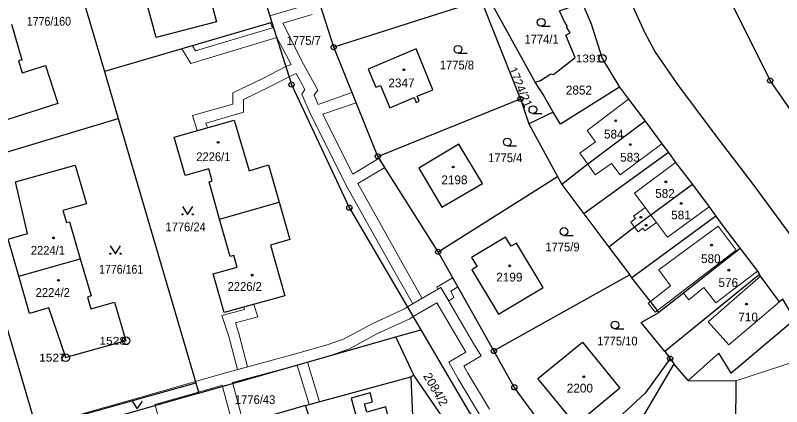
# Model space of a CAD drawing. Extents: x -679733 to -673243, y -1075091 to -1066557.
# Drawn here: x -676657.5 to -676509.5, y -1072340.3 to -1072264.6 of the extents above; entities that cross this region are included whole.
import ezdxf
from ezdxf.enums import TextEntityAlignment as Align

# ---------------------------------------------------------------- set-up
doc = ezdxf.new("R2010")
doc.units = 0
doc.header["$LTSCALE"] = 0.68
for name, color, linetype, lineweight in [('1', 7, 'Continuous', 25), ('13', 7, 'Continuous', 13), ('3', 7, 'Continuous', 25), ('4', 7, 'Continuous', 13), ('5', 7, 'Continuous', 25), ('8', 7, 'Continuous', 25)]:
    doc.layers.add(name, color=color, linetype=linetype, lineweight=lineweight)
doc.layers.add('2', color=7, linetype='Continuous')

msp = doc.modelspace()

# ---------------------------------------------------------------- linework, layer by layer
at = {"layer": '1'}
for p, q in [((-676621.45, -1072223.02), (-676607.94, -1072265.95)), ((-676650.7, -1072240.13), (-676640.33, -1072275.45)), ((-676557.11, -1072277.51), (-676565.21, -1072262.82)), ((-676559.93, -1072280.75), (-676558.34, -1072285.56)), ((-676668.3, -1072293.79), (-676637.65, -1072284.57)), ((-676531.34, -1072291.15), (-676547.67, -1072303)), ((-676575.84, -1072310.34), (-676552.78, -1072295.79)), ((-676618.06, -1072304), (-676606.53, -1072300.73)), ((-676547.67, -1072303), (-676542.82, -1072309.41)), ((-676522.18, -1072303.41), (-676538.38, -1072315.35)), ((-676542.82, -1072309.41), (-676538.81, -1072314.77)), ((-676656.87, -1072315.07), (-676644.98, -1072311.7)), ((-676538.81, -1072314.77), (-676565.06, -1072329.52)), ((-676580.53, -1072334.19), (-676584, -1072326.79)), ((-676527.49, -1072335.21), (-676530.28, -1072331.99)), ((-676601.48, -1072340.1), (-676581.08, -1072334.53)), ((-676580.53, -1072334.19), (-676581.08, -1072334.53)), ((-676571.12, -1072347.95), (-676580.53, -1072334.19)), ((-676648.79, -1072343.03), (-676622.64, -1072335.67)), ((-676622.64, -1072335.67), (-676622.05, -1072337.69)), ((-676622.05, -1072337.69), (-676652.85, -1072346.45))]:
    msp.add_line(p, q, dxfattribs=at)
for points in [[(-676478.96, -1072345.25), (-676486.76, -1072334.9), (-676494.15, -1072325.32), (-676502.31, -1072314.41), (-676514.96, -1072297.26), (-676522.29, -1072287.64), (-676529.49, -1072277.98), (-676533.98, -1072271.49), (-676535.89, -1072267.87), (-676539.19, -1072260.61), (-676540.03, -1072256.53), (-676540.61, -1072252.56), (-676541.33, -1072240.55), (-676542.21, -1072228.4), (-676543.04, -1072216.44), (-676543.58, -1072204.41), (-676544.01, -1072192.29), (-676544.34, -1072180.34), (-676543.76, -1072168.24), (-676542.51, -1072160.31), (-676535.08, -1072128.13), (-676536.59, -1072122.5)], [(-676459.56, -1072350.97), (-676462.01, -1072344.52), (-676467.19, -1072336.72), (-676484.08, -1072315.1), (-676500.58, -1072293.17), (-676511.67, -1072277.21), (-676520.52, -1072259.37), (-676526.16, -1072238.16), (-676527.35, -1072218.91), (-676525.48, -1072188.37), (-676523.69, -1072157.38), (-676522.2, -1072127.02), (-676522, -1072124.37)], [(-676565.06, -1072329.52), (-676575.84, -1072310.34), (-676587.49, -1072291.87), (-676596.02, -1072270.74), (-676602.38, -1072250.72), (-676608.74, -1072230.71), (-676615.09, -1072210.69)], [(-676619.62, -1072247.5), (-676617.65, -1072254.93), (-676621.29, -1072255.9), (-676618.67, -1072265.81), (-676630.33, -1072268.89), (-676632.37, -1072261.18), (-676627.63, -1072259.92), (-676628.3, -1072257.39), (-676628.98, -1072257.57), (-676631.09, -1072250.44)], [(-676654.21, -1072341.8), (-676668.3, -1072293.79), (-676681.73, -1072248.01)], [(-676587.49, -1072291.87), (-676559.93, -1072280.75), (-676566.85, -1072263.21), (-676567.46, -1072261.66), (-676596.02, -1072270.74)], [(-676557.11, -1072277.51), (-676556.08, -1072277.17), (-676554.04, -1072275.89), (-676553.55, -1072276.03), (-676549.34, -1072272.73), (-676551.19, -1072268.4), (-676550.33, -1072267.97), (-676550.99, -1072266.94), (-676550.89, -1072266.64), (-676551.49, -1072265.71), (-676552.37, -1072263.69), (-676547.98, -1072262.17)], [(-676547.98, -1072262.17), (-676546.24, -1072266.23), (-676544.12, -1072272.94), (-676540.77, -1072278.51)], [(-676658.26, -1072266.28), (-676656.3, -1072273.21), (-676656.92, -1072273.41), (-676656.19, -1072275.7), (-676651.69, -1072274.27), (-676649.33, -1072281.64), (-676660.82, -1072285.31), (-676663.91, -1072275.64), (-676667.68, -1072276.71), (-676669.73, -1072269.51)], [(-676607.94, -1072265.95), (-676640.33, -1072275.45), (-676637.65, -1072284.57), (-676622.64, -1072335.67)], [(-676607.94, -1072265.95), (-676604.16, -1072277.97), (-676593, -1072301.79), (-676579.2, -1072325.41)], [(-676553.58, -1072283.3), (-676555.52, -1072279.89), (-676557.11, -1072277.51)], [(-676540.77, -1072278.51), (-676552.19, -1072285.66), (-676553.58, -1072283.3)], [(-676540.77, -1072278.51), (-676539.07, -1072280.78), (-676535.8, -1072285.07)], [(-676553.58, -1072283.3), (-676558.34, -1072285.56), (-676552.78, -1072295.79), (-676551.95, -1072297.32)], [(-676618.06, -1072304), (-676620.1, -1072296.78), (-676619.47, -1072296.6), (-676620.13, -1072294.28), (-676624.72, -1072295.58), (-676626.83, -1072288.14), (-676615.23, -1072284.85), (-676612.32, -1072294.66), (-676608.6, -1072293.48), (-676606.53, -1072300.73)], [(-676535.8, -1072285.07), (-676546.91, -1072293.37), (-676551.95, -1072297.32), (-676547.67, -1072303)], [(-676535.8, -1072285.07), (-676532.61, -1072289.43), (-676531.34, -1072291.15)], [(-676531.34, -1072291.15), (-676529.94, -1072293.04), (-676526.71, -1072297.29)], [(-676656.87, -1072315.07), (-676658.93, -1072307.9), (-676655.18, -1072306.82), (-676657.51, -1072296.8), (-676645.96, -1072293.54), (-676643.77, -1072301.04), (-676648.33, -1072302.37), (-676647.66, -1072304.68), (-676647.08, -1072304.51), (-676644.98, -1072311.7)], [(-676526.71, -1072297.29), (-676534.74, -1072303.26), (-676537.87, -1072305.59), (-676542.82, -1072309.41)], [(-676526.71, -1072297.29), (-676523.47, -1072301.63), (-676522.18, -1072303.41)], [(-676606.53, -1072300.73), (-676604.47, -1072307.97), (-676608.22, -1072309.04), (-676605.45, -1072318.84), (-676617.16, -1072322.1), (-676619.28, -1072314.61), (-676614.69, -1072313.31), (-676615.33, -1072311.04), (-676616.01, -1072311.23), (-676618.06, -1072304)], [(-676522.18, -1072303.41), (-676520.82, -1072305.29), (-676517.47, -1072309.71)], [(-676517.47, -1072309.71), (-676528.4, -1072318.32), (-676533.17, -1072322.05)], [(-676517.47, -1072309.71), (-676514.11, -1072314.1), (-676513.75, -1072314.73)], [(-676644.98, -1072311.7), (-676642.88, -1072318.88), (-676643.6, -1072319.09), (-676642.93, -1072321.4), (-676638.36, -1072320.06), (-676636.17, -1072327.56), (-676647.8, -1072330.8), (-676651.06, -1072321.16), (-676654.81, -1072322.24), (-676656.87, -1072315.07)], [(-676533.17, -1072322.05), (-676533.44, -1072321.7), (-676534.82, -1072319.93), (-676538.38, -1072315.35), (-676538.81, -1072314.77)], [(-676506.94, -1072323.45), (-676509.25, -1072319.47), (-676509.86, -1072319.99), (-676513.54, -1072315.07), (-676513.75, -1072314.73), (-676532.03, -1072329.62)], [(-676532.03, -1072329.62), (-676536.57, -1072324.03), (-676533.17, -1072322.05)], [(-676506.94, -1072323.45), (-676519.24, -1072333.79), (-676521.58, -1072329.95), (-676527.49, -1072335.21)], [(-676622.05, -1072337.69), (-676584, -1072326.79), (-676579.2, -1072325.41)], [(-676579.2, -1072325.41), (-676569.86, -1072341.39), (-676563.3, -1072349.45), (-676561.58, -1072351.56)], [(-676556.87, -1072342.33), (-676561.11, -1072336.55), (-676565.06, -1072329.52)], [(-676532.03, -1072329.62), (-676531.01, -1072331), (-676530.28, -1072331.99)], [(-676531.01, -1072331), (-676535.82, -1072337.69), (-676548.96, -1072349.89)], [(-676530.28, -1072331.99), (-676537.47, -1072344.17), (-676540.69, -1072349.62)], [(-676581.08, -1072334.53), (-676580.71, -1072343.59), (-676575.76, -1072351.71), (-676592.57, -1072368.02), (-676592.35, -1072371.56)], [(-676527.49, -1072335.21), (-676518.31, -1072335.33), (-676518.43, -1072353.09), (-676518.84, -1072354.84)], [(-676595.21, -1072358.8), (-676601.48, -1072340.1), (-676620.34, -1072345.53)]]:
    msp.add_lwpolyline(points, dxfattribs=at)
for points in [[(-676579.48, -1072281.18), (-676579.87, -1072280.25), (-676576.85, -1072279), (-676580.11, -1072271.04), (-676589.35, -1072274.98), (-676587.88, -1072278.51), (-676586.98, -1072278.13), (-676585.17, -1072282.46), (-676580.47, -1072280.5), (-676580.08, -1072281.43)], [(-676571.83, -1072289.48), (-676579.57, -1072294.14), (-676575.12, -1072301.68), (-676567.24, -1072297.13)], [(-676568.28, -1072313.21), (-676569.31, -1072313.82), (-676564.2, -1072322.4), (-676555.56, -1072317.22), (-676560.71, -1072308.65), (-676561.75, -1072309.27), (-676562.82, -1072307.48), (-676569.37, -1072311.46)], [(-676547.94, -1072327.79), (-676540.7, -1072336.71), (-676549.25, -1072343.79), (-676556.57, -1072334.88)], [(-676596.84, -1072343.37), (-676593.48, -1072355.02), (-676583.89, -1072352.23), (-676586.2, -1072343.94), (-676585.15, -1072343.65), (-676585.96, -1072340.36), (-676589.63, -1072341.39), (-676590.07, -1072339.78), (-676588.51, -1072339.34), (-676588.99, -1072337.62), (-676592.65, -1072338.64), (-676591.72, -1072341.98)]]:
    msp.add_lwpolyline(points, close=True, dxfattribs=at)
at = {"layer": '13'}
for points in [[(-676602.88, -1072263.04), (-676608.35, -1072264.65), (-676607.94, -1072265.95), (-676608.25, -1072266.04), (-676607.84, -1072267.02), (-676622.7, -1072271.48), (-676623.32, -1072270.46), (-676625.36, -1072271.06), (-676623.62, -1072273.88), (-676607.01, -1072268.9), (-676604.25, -1072274.07), (-676605.25, -1072274.51), (-676609.68, -1072276.78), (-676615.52, -1072279.56), (-676615.5, -1072281.78), (-676623.28, -1072283.94), (-676622.39, -1072286.88), (-676620.43, -1072286.32), (-676620.69, -1072285.47), (-676613.44, -1072283.3), (-676613.46, -1072280.84), (-676608.78, -1072278.6), (-676604.63, -1072276.48), (-676603.26, -1072275.86), (-676601.58, -1072278.95), (-676602.16, -1072279.82)], [(-676602.16, -1072279.82), (-676600.57, -1072283.55), (-676596.08, -1072292.57), (-676593.66, -1072297.36), (-676584.97, -1072312.92), (-676580.74, -1072320.41), (-676578.91, -1072319.34), (-676583.13, -1072311.88), (-676591.35, -1072297.14), (-676586.15, -1072294), (-676587.25, -1072292.24), (-676592.3, -1072295.33), (-676594.2, -1072291.61), (-676598.14, -1072283.68), (-676591.69, -1072281.48), (-676592.49, -1072279.49), (-676599, -1072281.82), (-676599.76, -1072280.04), (-676599.11, -1072279.05), (-676601.83, -1072274), (-676605.83, -1072266.12), (-676600.18, -1072264.45)], [(-676565.94, -1072340.81), (-676570.11, -1072333.8), (-676570.86, -1072332.46), (-676567.5, -1072330.45), (-676568.99, -1072328.05), (-676575.29, -1072317.25), (-676581.77, -1072321), (-676582.32, -1072321.37), (-676588.58, -1072324.24), (-676594.01, -1072327.18), (-676597.11, -1072328.28), (-676602.69, -1072329.88), (-676617.09, -1072333.8), (-676622.72, -1072335.41), (-676632.14, -1072338.12), (-676648.5, -1072342.8)], [(-676613.91, -1072341.89), (-676615.5, -1072335.81), (-676615.55, -1072335.62), (-676603.06, -1072332.25), (-676600.76, -1072339.9), (-676598.76, -1072339.36), (-676601.09, -1072331.69), (-676596.61, -1072330.4), (-676592.99, -1072329.08), (-676587.68, -1072326.2), (-676581.32, -1072323.3), (-676580.68, -1072322.88), (-676576.07, -1072320.19), (-676570.51, -1072329.74), (-676573.78, -1072331.7), (-676571.97, -1072334.9), (-676567.66, -1072342.11)], [(-676628.23, -1072347.76), (-676630.5, -1072340.09), (-676630.55, -1072339.91), (-676622.11, -1072337.49), (-676617.52, -1072336.17), (-676617.47, -1072336.38), (-676615.89, -1072342.41)]]:
    msp.add_lwpolyline(points, dxfattribs=at)
for points in [[(-676572.79, -1072319.17), (-676573.39, -1072317.98), (-676572.02, -1072317.14), (-676573.03, -1072315.35), (-676576.09, -1072317.18), (-676575.88, -1072317.59), (-676575.29, -1072317.25), (-676573.77, -1072319.85)], [(-676612.65, -1072332.59), (-676614.32, -1072326.14), (-676615.01, -1072324.05), (-676610.67, -1072322.9), (-676611.44, -1072320.51), (-676613.41, -1072321.06), (-676613.27, -1072321.48), (-676617.61, -1072322.63), (-676616.28, -1072326.72), (-676614.62, -1072333.13)]]:
    msp.add_lwpolyline(points, close=True, dxfattribs=at)
at = {"layer": '3'}
for p, q in [((-676555.933, -1072266.69), (-676554.183, -1072266.69)), ((-676571.983, -1072271.9), (-676570.233, -1072271.9)), ((-676557.523, -1072283.58), (-676555.773, -1072283.58)), ((-676562.453, -1072289.85), (-676560.703, -1072289.85)), ((-676551.513, -1072307.16), (-676549.763, -1072307.16)), ((-676541.673, -1072325.23), (-676539.923, -1072325.23))]:
    msp.add_line(p, q, dxfattribs=at)
for points in [[(-676625.25, -1072301.589), (-676624.25, -1072303.09), (-676623.25, -1072301.589)], [(-676639.18, -1072309.209), (-676638.18, -1072310.71), (-676637.18, -1072309.209)], [(-676634.98, -1072339.229), (-676633.98, -1072340.73), (-676632.98, -1072339.229)]]:
    msp.add_lwpolyline(points, dxfattribs=at)
for centre, radius in [((-676555.9329, -1072265.9398), 0.75), ((-676571.9829, -1072271.1498), 0.75), ((-676557.5229, -1072282.8298), 0.75), ((-676562.4529, -1072289.0998), 0.75), ((-676625.25, -1072303.0895), 0.1), ((-676623.25, -1072303.0895), 0.1), ((-676551.5129, -1072306.4098), 0.75), ((-676639.18, -1072310.7095), 0.1), ((-676637.18, -1072310.7095), 0.1), ((-676541.6729, -1072324.4798), 0.75)]:
    msp.add_circle(centre, radius, dxfattribs=at)
at = {"layer": '4'}
for p, q in [((-676547.01, -1072286.86), (-676539.07, -1072280.78)), ((-676545.43, -1072289.07), (-676547.01, -1072286.86)), ((-676548.45, -1072291.22), (-676545.43, -1072289.07)), ((-676540.66, -1072295.42), (-676532.61, -1072289.43)), ((-676546.91, -1072293.37), (-676548.45, -1072291.22)), ((-676546.91, -1072293.37), (-676545.48, -1072295.47)), ((-676545.48, -1072295.47), (-676542.33, -1072293.23)), ((-676542.33, -1072293.23), (-676540.66, -1072295.42)), ((-676529.94, -1072293.04), (-676537.88, -1072298.98)), ((-676537.88, -1072298.98), (-676535.83, -1072301.79)), ((-676535.83, -1072301.79), (-676538.06, -1072303.47)), ((-676535.83, -1072301.79), (-676534.74, -1072303.26)), ((-676531.53, -1072307.53), (-676523.47, -1072301.63)), ((-676537.71, -1072303.89), (-676538.62, -1072304.59)), ((-676538.06, -1072303.47), (-676537.71, -1072303.89)), ((-676534.74, -1072303.26), (-676533.67, -1072304.69)), ((-676538.62, -1072304.59), (-676537.87, -1072305.59)), ((-676537.87, -1072305.59), (-676537.19, -1072306.5)), ((-676535.92, -1072306.3), (-676533.67, -1072304.69)), ((-676533.67, -1072304.69), (-676531.53, -1072307.53)), ((-676521.73, -1072305.35), (-676529.44, -1072311.06)), ((-676518.24, -1072310.01), (-676521.73, -1072305.35)), ((-676537.19, -1072306.5), (-676536.31, -1072305.79)), ((-676536.31, -1072305.79), (-676535.92, -1072306.3)), ((-676533.44, -1072321.7), (-676518.24, -1072310.01)), ((-676529.44, -1072311.06), (-676533.16, -1072313.8)), ((-676533.16, -1072313.8), (-676530.94, -1072316.92)), ((-676514.11, -1072314.1), (-676522.19, -1072320.23)), ((-676523.65, -1072323.86), (-676513.54, -1072315.07)), ((-676530.94, -1072316.92), (-676534.82, -1072319.93)), ((-676524.49, -1072317.27), (-676527.4, -1072319.61)), ((-676522.19, -1072320.23), (-676524.49, -1072317.27)), ((-676527.4, -1072319.61), (-676528.4, -1072318.32)), ((-676534.82, -1072319.93), (-676535.23, -1072320.25)), ((-676535.23, -1072320.25), (-676533.88, -1072322.04)), ((-676519.69, -1072328.34), (-676509.86, -1072319.99)), ((-676533.88, -1072322.04), (-676533.44, -1072321.7)), ((-676523.65, -1072323.86), (-676519.69, -1072328.34)), ((-676518.31, -1072335.33), (-676502.98, -1072330.28))]:
    msp.add_line(p, q, dxfattribs=at)
at = {"layer": '5'}
for centre in [(-676582.4668, -1072275.1092), (-676541.5268, -1072284.9792), (-676618.3268, -1072289.1492), (-676538.6968, -1072289.5892), (-676572.9268, -1072293.9292), (-676531.8368, -1072296.7892), (-676528.8568, -1072300.9692), (-676536.6568, -1072303.6592), (-676535.6468, -1072305.1992), (-676650.1468, -1072307.6492), (-676523.0068, -1072309.0592), (-676562.0068, -1072313.0592), (-676519.6768, -1072313.8992), (-676649.2068, -1072315.8592), (-676611.7868, -1072314.8592), (-676516.2668, -1072320.4392), (-676547.7068, -1072334.4992)]:
    msp.add_circle(centre, 0.175, dxfattribs=at)
at = {"layer": '8'}
for centre, radius in [((-676596.02, -1072270.7399), 0.5), ((-676596.02, -1072270.7399), 0.0303), ((-676544.12, -1072272.9198), 0.75), ((-676544.12, -1072272.9198), 0.03), ((-676604.16, -1072277.9699), 0.5), ((-676511.67, -1072277.2099), 0.5), ((-676511.67, -1072277.2099), 0.0303), ((-676604.16, -1072277.9699), 0.0303), ((-676559.93, -1072280.7499), 0.5), ((-676559.93, -1072280.7499), 0.0303), ((-676587.49, -1072291.8699), 0.5), ((-676587.49, -1072291.8699), 0.0303), ((-676593, -1072301.7899), 0.5), ((-676593, -1072301.7899), 0.0303), ((-676575.84, -1072310.3399), 0.5), ((-676575.84, -1072310.3399), 0.0303), ((-676636.15, -1072327.5498), 0.75), ((-676636.15, -1072327.5498), 0.03), ((-676565.06, -1072329.5199), 0.5), ((-676647.8, -1072330.8198), 0.75), ((-676647.8, -1072330.8198), 0.03), ((-676565.06, -1072329.5199), 0.0303), ((-676531.01, -1072330.9999), 0.5), ((-676531.01, -1072330.9999), 0.0303), ((-676561.11, -1072336.5499), 0.5), ((-676561.11, -1072336.5499), 0.0303)]:
    msp.add_circle(centre, radius, dxfattribs=at)

# ---------------------------------------------------------------- texts
at = {"layer": '2'}
for s, width, p in [('1776/160', 0.9, (-676655.31, -1072266.58)), ('1775/7', 0.95, (-676605.12, -1072270.3)), ('1774/1', 0.95, (-676559.15, -1072270.04)), ('1775/8', 0.95, (-676575.51, -1072275.04)), ('2226/1', 0.95, (-676622.57, -1072292.79)), ('1775/4', 0.95, (-676566.17, -1072292.989)), ('1776/24', 0.95, (-676628.53, -1072306.37)), ('1775/9', 0.95, (-676555.11, -1072310.249)), ('2224/1', 0.95, (-676654.55, -1072310.9)), ('1776/161', 0.9, (-676641.35, -1072314.56)), ('2226/2', 0.95, (-676616.51, -1072317.89)), ('2224/2', 0.95, (-676653.6, -1072319.05)), ('1775/10', 0.95, (-676545.1, -1072328.45)), ('1776/43', 0.95, (-676615.1, -1072339.79))]:
    msp.add_text(s, height=1.7, dxfattribs=dict(at, width=width)).set_placement(p)
for s, rotation, p in [('1724/21', 293, (-676562.332, -1072275.032)), ('2084/2', 300, (-676578.776, -1072334.365))]:
    msp.add_text(s, height=1.7, rotation=rotation, dxfattribs=at).set_placement(p)
for s, p in [('2347', (-676585.45, -1072278.509)), ('584', (-676543.79, -1072288.42)), ('583', (-676540.67, -1072292.89)), ('2198', (-676575.21, -1072297.259)), ('582', (-676533.89, -1072299.89)), ('581', (-676530.81, -1072304.06)), ('580', (-676525.04, -1072312.519)), ('2199', (-676564.6, -1072316.08)), ('576', (-676521.67, -1072317.14)), ('710', (-676517.83, -1072323.81)), ('2200', (-676550.97, -1072337.56))]:
    msp.add_text(s, height=1.7, dxfattribs=at).set_placement(p)
msp.add_text('2852', height=1.7, dxfattribs=at).set_placement((-676548.63, -1072279.9), align=Align.CENTER)
at = {"layer": '8', "width": 1.15}
for s, p in [('1391', (-676544.119, -1072273.669)), ('1528', (-676636.149, -1072328.3)), ('1527', (-676647.799, -1072331.57))]:
    msp.add_text(s, height=1.5, dxfattribs=at).set_placement(p, align=Align.RIGHT)

doc.saveas('drawing.dxf')
